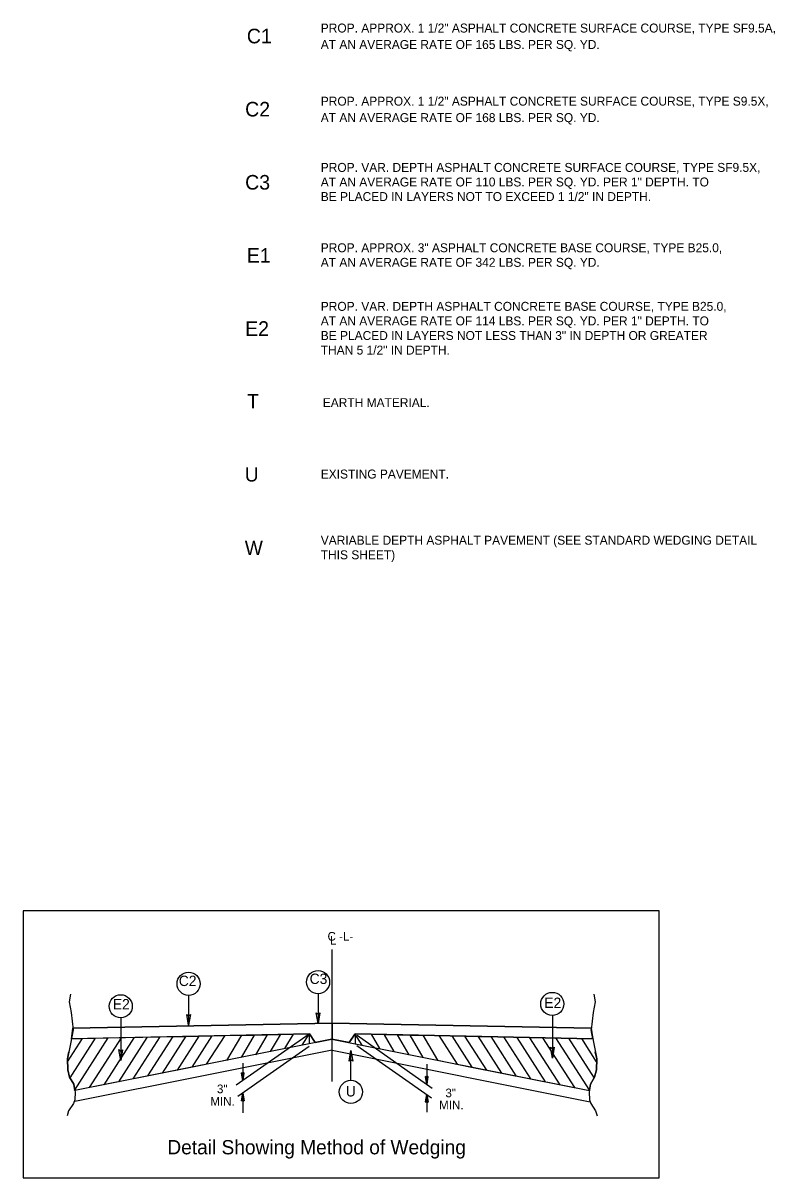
# Model space of a CAD drawing. Extents: x 1718167 to 1721223, y 797898 to 799800.
# Drawn here: x 1718167 to 1718735, y 798128 to 799000 of the extents above; entities that cross this region are included whole.
import ezdxf

# ---------------------------------------------------------------- set-up
doc = ezdxf.new("R2010")
doc.units = 0
for name, color, linetype in [('Default', 7, 'Continuous'), ('Prop Pavement Schedule Description CELL', 7, 'Continuous'), ('Prop Shade Heavy', 7, 'Continuous'), ('Typical Detail Wedge2 CELL', 7, 'Continuous'), ('Typical ID Circle CELL', 7, 'Continuous'), ('Typical Terminator CELL', 7, 'Continuous'), ('Typical Text Centerline CELL', 7, 'Continuous'), ('Typical Text General CELL', 7, 'Continuous'), ('Typical Text ID Circle CELL', 7, 'Continuous')]:
    doc.layers.add(name, color=color, linetype=linetype)

# ---------------------------------------------------------------- blocks, each defined once
blk = doc.blocks.new('TERMINATOR')
at = {"layer": 'Typical Terminator CELL'}
blk.add_lwpolyline([(-0.469, 0.081), (0, 0), (-0.471, -0.083), (-0.411, 0)], close=True, dxfattribs=at)

msp = doc.modelspace()

# ---------------------------------------------------------------- linework, layer by layer
at = {"layer": 'Default'}
msp.add_lwpolyline([(1718167.23, 798127.81), (1718647.48, 798127.81), (1718647.48, 798329.47), (1718167.23, 798329.47)], close=True, dxfattribs=at)
at = {"layer": 'Prop Shade Heavy'}
for points in [[(1718212.05, 798233.13), (1718221.79, 798233.32), (1718231.52, 798233.51), (1718270.78, 798234.3), (1718280.51, 798234.49), (1718290.25, 798234.69), (1718300.2, 798234.89), (1718309.93, 798235.08), (1718319.67, 798235.28), (1718332.08, 798235.52), (1718341.85, 798235.72), (1718341.85, 798235.72), (1718341.85, 798235.72), (1718351.52, 798235.91), (1718371.04, 798236.3), (1718383.42, 798236.55), (1718387.82, 798230.1), (1718400.3, 798232.7), (1718400.6, 798232.64), (1718400.6, 798232.64), (1718400.6, 798244.73), (1718400.59, 798244.73), (1718390, 798244.52), (1718389.97, 798244.33), (1718389.94, 798244.52), (1718204.85, 798240.82), (1718204.82, 798240.64), (1718204.93, 798239.57), (1718203.76, 798233.17), (1718203.73, 798232.96), (1718212.05, 798233.13)], [(1718569.67, 798233.51), (1718579.4, 798233.32), (1718589.14, 798233.13), (1718597.47, 798232.96), (1718596.26, 798239.57), (1718596.37, 798240.67), (1718596.35, 798240.82), (1718400.61, 798244.73), (1718400.6, 798244.73), (1718400.6, 798232.64), (1718400.6, 798232.64), (1718400.6, 798232.64), (1718413.37, 798230.1), (1718417.81, 798236.4), (1718417.91, 798236.55), (1718430.15, 798236.3), (1718449.67, 798235.91), (1718459.34, 798235.72), (1718459.34, 798235.72), (1718459.34, 798235.72), (1718469.12, 798235.53), (1718481.53, 798235.28), (1718491.27, 798235.08), (1718501, 798234.89), (1718510.95, 798234.69), (1718520.69, 798234.49), (1718530.42, 798234.3), (1718569.67, 798233.51)]]:
    msp.add_lwpolyline(points, dxfattribs=at)
at = {"layer": 'Typical Detail Wedge2 CELL'}
for p, q in [((1718400.6, 798200.67), (1718400.6, 798300.41)), ((1718400.6, 798200.67), (1718400.6, 798268.79)), ((1718203.73, 798232.96), (1718204.85, 798240.82)), ((1718400.59, 798244.73), (1718204.85, 798240.82)), ((1718204.85, 798240.82), (1718400.59, 798244.73)), ((1718400.59, 798244.73), (1718596.35, 798240.82)), ((1718400.61, 798244.73), (1718596.35, 798240.82)), ((1718596.35, 798240.82), (1718597.47, 798232.96)), ((1718200.82, 798215.59), (1718212.09, 798233.18)), ((1718202.65, 798203.44), (1718221.82, 798233.38)), ((1718383.42, 798236.55), (1718203.73, 798232.96)), ((1718383.42, 798236.55), (1718203.73, 798232.96)), ((1718206.03, 798193.72), (1718231.56, 798233.57)), ((1718400.89, 798232.7), (1718206.32, 798193.78)), ((1718217.38, 798195.99), (1718241.43, 798233.53)), ((1718228.4, 798198.19), (1718251.16, 798233.72)), ((1718283.78, 798209.27), (1718300.26, 798234.99)), ((1718294.81, 798211.48), (1718310, 798235.19)), ((1718305.83, 798213.68), (1718319.74, 798235.38)), ((1718332.08, 798235.52), (1718320.96, 798216.46)), ((1718383.2, 798236.41), (1718328.05, 798197.78)), ((1718341.85, 798235.72), (1718332, 798218.82)), ((1718351.52, 798235.91), (1718342.68, 798220.76)), ((1718361.26, 798235.89), (1718353.94, 798223.34)), ((1718371.09, 798236.39), (1718364.7, 798225.45)), ((1718377.86, 798228.18), (1718383.17, 798236.48)), ((1718383.17, 798236.48), (1718383.17, 798229.66)), ((1718387.82, 798230.1), (1718383.42, 798236.55)), ((1718383.42, 798236.34), (1718387.82, 798230.1)), ((1718400.3, 798232.7), (1718387.82, 798230.1)), ((1718400.3, 798232.7), (1718594.88, 798193.78)), ((1718413.37, 798230.1), (1718400.3, 798232.7)), ((1718417.91, 798236.55), (1718413.37, 798230.1)), ((1718417.91, 798236.55), (1718413.37, 798230.1)), ((1718417.63, 798236.41), (1718417.91, 798236.39)), ((1718417.91, 798236.55), (1718597.47, 798232.96)), ((1718597.47, 798232.96), (1718417.91, 798236.55)), ((1718423.34, 798228.18), (1718418.03, 798236.48)), ((1718418.03, 798236.48), (1718418.03, 798228.96)), ((1718419.41, 798235.51), (1718476.23, 798195.71)), ((1718430.1, 798236.39), (1718436.49, 798225.45)), ((1718439.93, 798235.89), (1718447.25, 798223.34)), ((1718449.67, 798235.91), (1718458.51, 798220.76)), ((1718459.34, 798235.72), (1718469.19, 798218.82)), ((1718469.12, 798235.52), (1718480.07, 798216.74)), ((1718400.52, 798224.32), (1718206.25, 798185.46)), ((1718383.33, 798226.96), (1718329.36, 798189.18)), ((1718400.67, 798224.32), (1718595.39, 798185.37)), ((1718419.33, 798227.77), (1718475.6, 798188.38)), ((1718314.96, 798215.51), (1718295.26, 798211.56)), ((1718321.1, 798216.74), (1718314.96, 798215.51)), ((1718333.07, 798214.42), (1718333.07, 798201.3)), ((1718472.08, 798213.67), (1718472.08, 798198.63)), ((1718480.07, 798216.74), (1718505.94, 798211.56)), ((1718295.26, 798211.56), (1718206.32, 798193.78)), ((1718333.07, 798201.3), (1718332.05, 798207.05)), ((1718333.07, 798206.3), (1718332.05, 798207.05)), ((1718333.07, 798201.3), (1718332.2, 798206.94)), ((1718332.34, 798206.84), (1718333.07, 798201.3)), ((1718333.07, 798201.3), (1718332.49, 798206.74)), ((1718332.64, 798206.63), (1718333.07, 798201.3)), ((1718333.07, 798201.3), (1718332.78, 798206.52)), ((1718332.93, 798206.41), (1718333.07, 798201.3)), ((1718333.07, 798201.3), (1718334.09, 798207.05)), ((1718334.09, 798207.05), (1718333.07, 798206.3)), ((1718333.95, 798206.94), (1718333.07, 798201.3)), ((1718333.07, 798201.3), (1718333.79, 798206.84)), ((1718333.65, 798206.74), (1718333.07, 798201.3)), ((1718333.07, 798201.3), (1718333.5, 798206.63)), ((1718333.36, 798206.52), (1718333.07, 798201.3)), ((1718333.07, 798201.3), (1718333.21, 798206.41)), ((1718333.07, 798206.3), (1718333.07, 798201.3)), ((1718472.08, 798198.63), (1718471.06, 798204.38)), ((1718472.08, 798203.63), (1718471.06, 798204.38)), ((1718472.08, 798198.63), (1718471.21, 798204.27)), ((1718471.35, 798204.17), (1718472.08, 798198.63)), ((1718472.08, 798198.63), (1718471.5, 798204.06)), ((1718471.64, 798203.95), (1718472.08, 798198.63)), ((1718472.08, 798198.63), (1718471.78, 798203.85)), ((1718471.93, 798203.74), (1718472.08, 798198.63)), ((1718472.08, 798198.63), (1718473.09, 798204.38)), ((1718473.09, 798204.38), (1718472.08, 798203.63)), ((1718472.94, 798204.27), (1718472.08, 798198.63)), ((1718472.08, 798198.63), (1718472.8, 798204.17)), ((1718472.65, 798204.06), (1718472.08, 798198.63)), ((1718472.08, 798198.63), (1718472.51, 798203.95)), ((1718472.37, 798203.85), (1718472.08, 798198.63)), ((1718472.08, 798198.63), (1718472.22, 798203.74)), ((1718472.08, 798203.63), (1718472.08, 798198.63)), ((1718505.94, 798211.56), (1718594.88, 798193.78)), ((1718333.07, 798191.77), (1718332.05, 798186.02)), ((1718332.05, 798186.02), (1718333.07, 798186.77)), ((1718332.2, 798186.13), (1718333.07, 798191.77)), ((1718333.07, 798191.77), (1718332.34, 798186.23)), ((1718332.49, 798186.35), (1718333.07, 798191.77)), ((1718333.07, 798191.77), (1718332.64, 798186.45)), ((1718332.78, 798186.55), (1718333.07, 798191.77)), ((1718333.07, 798191.77), (1718332.93, 798186.66)), ((1718333.07, 798191.77), (1718333.07, 798177)), ((1718333.07, 798191.77), (1718334.09, 798186.02)), ((1718333.07, 798186.77), (1718333.07, 798191.77)), ((1718333.21, 798186.66), (1718333.07, 798191.77)), ((1718333.07, 798191.77), (1718333.36, 798186.55)), ((1718333.5, 798186.45), (1718333.07, 798191.77)), ((1718333.07, 798191.77), (1718333.65, 798186.35)), ((1718333.79, 798186.23), (1718333.07, 798191.77)), ((1718333.07, 798191.77), (1718333.95, 798186.13)), ((1718333.07, 798186.77), (1718334.09, 798186.02)), ((1718472.08, 798190.84), (1718471.06, 798185.08)), ((1718471.06, 798185.08), (1718472.08, 798185.83)), ((1718471.21, 798185.2), (1718472.08, 798190.84)), ((1718472.08, 798190.84), (1718471.35, 798185.3)), ((1718471.5, 798185.41), (1718472.08, 798190.84)), ((1718472.08, 798190.84), (1718471.64, 798185.51)), ((1718471.78, 798185.61), (1718472.08, 798190.84)), ((1718472.08, 798190.84), (1718471.93, 798185.72)), ((1718472.08, 798190.84), (1718472.08, 798177.38)), ((1718472.08, 798190.84), (1718473.09, 798185.08)), ((1718472.08, 798185.83), (1718472.08, 798190.84)), ((1718472.22, 798185.72), (1718472.08, 798190.84)), ((1718472.08, 798190.84), (1718472.37, 798185.61)), ((1718472.51, 798185.51), (1718472.08, 798190.84)), ((1718472.08, 798190.84), (1718472.65, 798185.41)), ((1718472.8, 798185.3), (1718472.08, 798190.84)), ((1718472.08, 798190.84), (1718472.94, 798185.2)), ((1718472.08, 798185.83), (1718473.09, 798185.08))]:
    msp.add_line(p, q, dxfattribs=at)
for points in [[(1718203.03, 798266.66), (1718201.98, 798260.92), (1718203.55, 798252.77), (1718204.93, 798239.57), (1718203.03, 798229.15), (1718200.77, 798217.87), (1718200.95, 798209.36), (1718202.34, 798203.98), (1718205.47, 798198.59), (1718206.5, 798192.69), (1718206.33, 798186.79), (1718205.29, 798184), (1718201.64, 798178.45), (1718200.43, 798174.63)], [(1718598.16, 798266.66), (1718599.21, 798260.92), (1718597.65, 798252.77), (1718596.26, 798239.57), (1718598.16, 798229.15), (1718600.42, 798217.87), (1718600.25, 798209.36), (1718598.85, 798203.98), (1718595.73, 798198.59), (1718594.7, 798192.69), (1718594.86, 798186.79), (1718595.9, 798184), (1718599.55, 798178.45), (1718600.76, 798174.63)], [(1718239.43, 798200.4), (1718260.9, 798233.92)], [(1718250.46, 798202.61), (1718270.83, 798234.39)], [(1718261.49, 798204.81), (1718280.57, 798234.58)], [(1718272.51, 798207.02), (1718290.3, 798234.78)], [(1718495.37, 798213.68), (1718481.47, 798235.38)], [(1718506.39, 798211.47), (1718491.2, 798235.19)], [(1718517.41, 798209.27), (1718500.93, 798234.99)], [(1718528.69, 798207.02), (1718510.9, 798234.78)], [(1718539.71, 798204.81), (1718520.63, 798234.58)], [(1718550.73, 798202.61), (1718530.37, 798234.39)], [(1718561.76, 798200.4), (1718540.29, 798233.92)], [(1718572.79, 798198.2), (1718550.03, 798233.72)], [(1718583.81, 798195.99), (1718559.76, 798233.53)], [(1718595.16, 798193.72), (1718569.63, 798233.57)], [(1718598.67, 798203.25), (1718579.37, 798233.38)], [(1718600.38, 798215.58), (1718589.1, 798233.18)], [(1718206.31, 798193.78), (1718205.47, 798198.59), (1718202.34, 798203.98), (1718200.95, 798209.36), (1718200.77, 798217.87), (1718201.82, 798223.1)], [(1718594.88, 798193.78), (1718595.73, 798198.59), (1718598.85, 798203.98), (1718600.25, 798209.36), (1718600.42, 798217.87), (1718599.37, 798223.1)]]:
    msp.add_lwpolyline(points, dxfattribs=at)
at = {"layer": 'Typical ID Circle CELL'}
for p, q in [((1718292.21, 798265.67), (1718292.21, 798243.07)), ((1718389.97, 798266.92), (1718389.97, 798244.33)), ((1718240.97, 798248.69), (1718240.97, 798216.56)), ((1718566.92, 798250.48), (1718566.92, 798218.35)), ((1718414.76, 798201.53), (1718414.76, 798224.13))]:
    msp.add_line(p, q, dxfattribs=at)
for centre in [(1718292.21, 798274.41), (1718389.97, 798275.67), (1718240.96, 798257.43), (1718566.91, 798259.22), (1718414.76, 798192.79)]:
    msp.add_circle(centre, 8.74, dxfattribs=at)

# ---------------------------------------------------------------- block references
at = {"layer": 'Typical Terminator CELL', "xscale": 17.2740059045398, "yscale": 17.2740059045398}
for p, rotation in [((1718292.21, 798243.07), -90), ((1718389.97, 798244.33), -90), ((1718240.97, 798216.56), -90), ((1718414.76, 798224.13), 90), ((1718566.92, 798218.35), -90)]:
    msp.add_blockref('TERMINATOR', p, dxfattribs=dict(at, rotation=rotation))

# ---------------------------------------------------------------- texts
at = {"layer": 'Default'}
for s, height, p in [('PROP. VAR. DEPTH ASPHALT CONCRETE SURFACE COURSE, TYPE SF9.5X,', 6.75, (1718392.03, 798887.67)), ('C3', 11.025, (1718334.91, 798874.29)), ('AT AN AVERAGE RATE OF 110 LBS. PER SQ. YD. PER 1" DEPTH. TO', 6.75, (1718392.03, 798876.66)), ('BE PLACED IN LAYERS NOT TO EXCEED 1 1/2" IN DEPTH.', 6.75, (1718392.03, 798865.64))]:
    msp.add_text(s, height=height, dxfattribs=at).set_placement(p)
at = {"layer": 'Prop Pavement Schedule Description CELL'}
for s, height, p in [('PROP. APPROX. 1 1/2" ASPHALT CONCRETE SURFACE COURSE, TYPE SF9.5A,', 6.75, (1718392.03, 798992.94)), ('C1', 11.025, (1718336.2, 798984.76)), ('AT AN AVERAGE RATE OF 165 LBS. PER SQ. YD.', 6.75, (1718392.03, 798980.51)), ('PROP. APPROX. 1 1/2" ASPHALT CONCRETE SURFACE COURSE, TYPE S9.5X,', 6.75, (1718392.03, 798937.7)), ('C2', 11.025, (1718334.91, 798929.52)), ('AT AN AVERAGE RATE OF 168 LBS. PER SQ. YD.', 6.75, (1718392.03, 798925.27)), ('PROP. APPROX. 3" ASPHALT CONCRETE BASE COURSE, TYPE B25.0,', 6.75, (1718392.03, 798826.99)), ('E1', 11.025, (1718336.2, 798819.06)), ('AT AN AVERAGE RATE OF 342 LBS. PER SQ. YD.', 6.75, (1718392.03, 798815.97)), ('PROP. VAR. DEPTH ASPHALT CONCRETE BASE COURSE, TYPE B25.0,', 6.75, (1718392.03, 798782.73)), ('E2', 11.025, (1718334.91, 798763.83)), ('AT AN AVERAGE RATE OF 114 LBS. PER SQ. YD. PER 1" DEPTH. TO', 6.75, (1718392.03, 798771.72)), ('BE PLACED IN LAYERS NOT LESS THAN 3" IN DEPTH OR GREATER', 6.75, (1718392.03, 798760.7)), ('THAN 5 1/2" IN DEPTH.', 6.75, (1718392.03, 798749.69)), ('T ', 10.8, (1718336.47, 798709.12)), ('EARTH MATERIAL.', 6.75, (1718393.57, 798710)), ('U ', 10.8, (1718334.67, 798653.77)), ('EXISTING PAVEMENT.', 6.75, (1718392.03, 798656.07)), ('W ', 10.8, (1718334.67, 798598.27)), ('VARIABLE DEPTH ASPHALT PAVEMENT (SEE STANDARD WEDGING DETAIL', 6.75, (1718392.03, 798606.08)), ('THIS SHEET)', 6.75, (1718392.03, 798595.07))]:
    msp.add_text(s, height=height, dxfattribs=at).set_placement(p)
at = {"layer": 'Typical Detail Wedge2 CELL'}
for p in [(1718308.59, 798182.43), (1718481.42, 798179.58)]:
    msp.add_text('MIN.', height=6.54, dxfattribs=at).set_placement(p)
at = {"layer": 'Typical Text Centerline CELL'}
for s, p in [('C -L-', (1718397.14, 798306.99)), ('L', (1718399.05, 798303.94)), ('3"', (1718313.64, 798191.77)), ('3"', (1718486.16, 798188.73))]:
    msp.add_text(s, height=6.54, dxfattribs=at).set_placement(p)
at = {"layer": 'Typical Text General CELL'}
msp.add_text('Detail Showing Method of Wedging', height=10.7943, dxfattribs=at).set_placement((1718276.18, 798145.61))
at = {"layer": 'Typical Text ID Circle CELL'}
for s, height, p in [('C3', 7.826, (1718383.64, 798274.29)), ('C2', 7.826, (1718284.81, 798272.74)), ('E2', 7.826, (1718234.99, 798255.12)), ('E2', 7.826, (1718560.86, 798256.16)), ('U', 7.83, (1718410.94, 798189.33))]:
    msp.add_text(s, height=height, dxfattribs=at).set_placement(p)

doc.saveas('drawing.dxf')
